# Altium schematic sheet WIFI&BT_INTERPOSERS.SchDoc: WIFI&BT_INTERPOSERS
size A3; Author: P.A.; CompanyName: STMicroelectronics; Organization: Microcontrollers Division; Address1: 12, Rue Jules HOROWITZ; Address2: 38019 Grenoble; Address3: FRANCE; DocumentNumber: 13; Revision: C; SheetNumber: 13; SheetTotal: 16; Project: STM32L4S5AII6_IOT_V2; PageSetup: Record=PageOptions¦CenterHorizontal=True¦CenterVertical=True¦PrintScale=1.00¦XCorrection=1.00¦YCorrection=1.00¦PrintKind=1¦BorderSize=5000000¦LeftOffset=0¦BottomOffset=0¦Orientation=2¦PaperLength=1000¦PaperWidth=1000¦Scale=100¦PaperSource=7¦PrintQuality=-3¦MediaType=1¦DitherType=10¦PrintScaleMode=1¦PaperKind=Letter¦PaperIndex=1
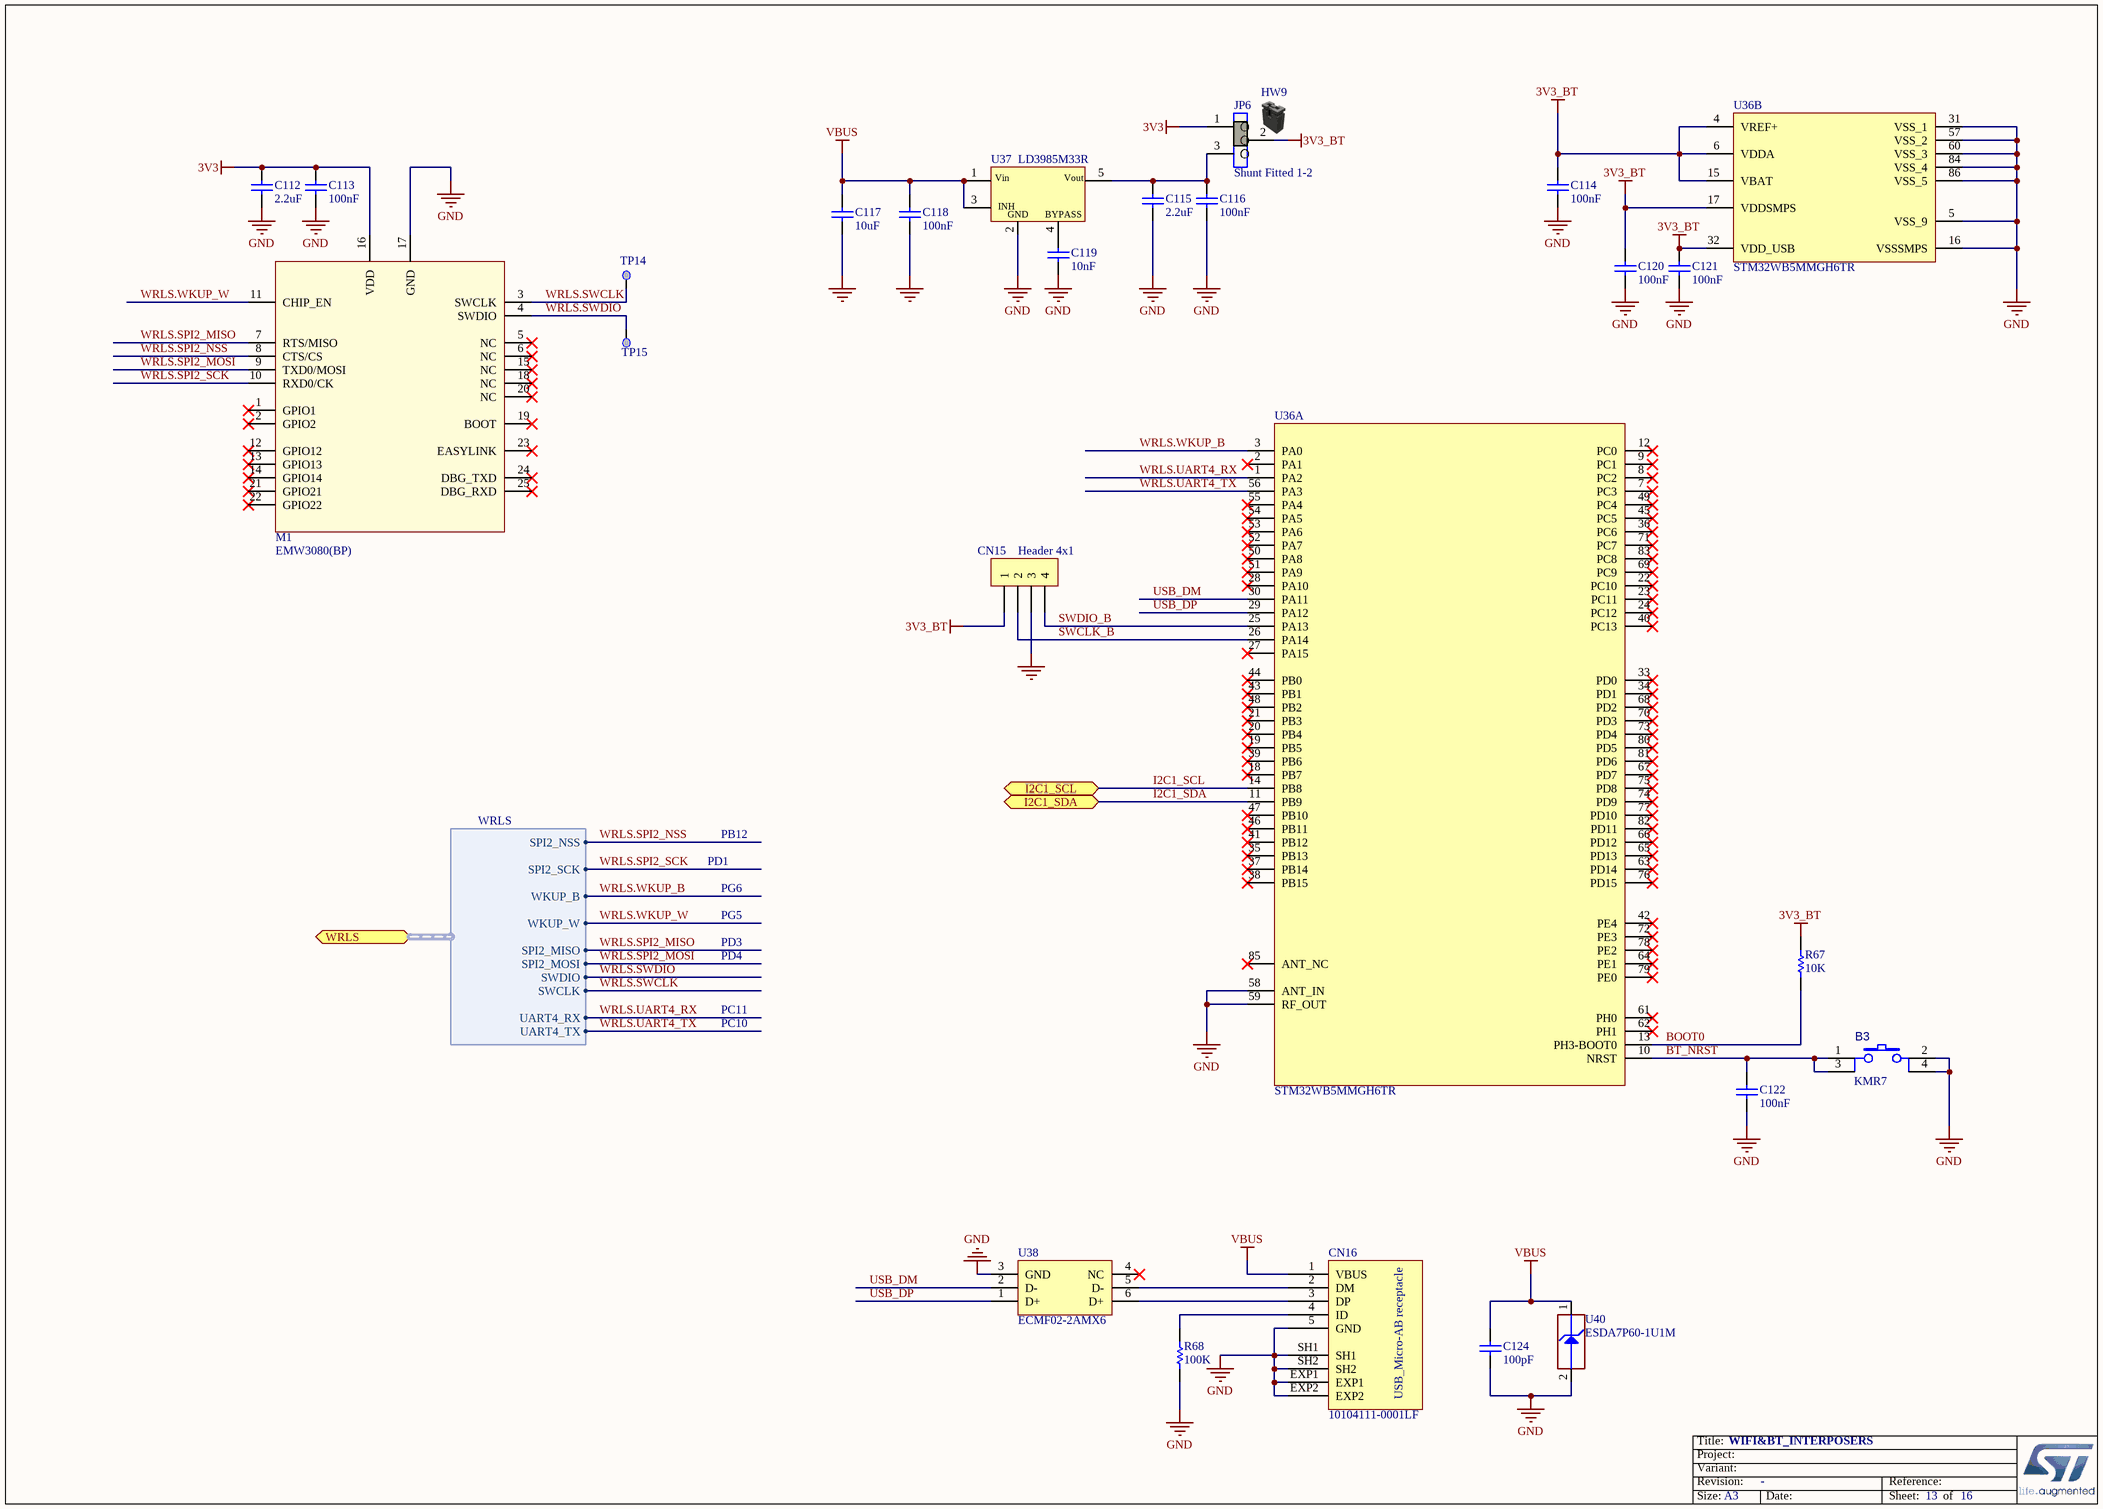
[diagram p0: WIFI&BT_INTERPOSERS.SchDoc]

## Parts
B3  value KMR7  [SWI_C&K_KMR721NG-LFS]  (hidden comment: SW-PUSH-CMS_KMR_NG)
C112  value 2.2uF  [C0603]  (hidden comment: Capacitor)
C113  value 100nF  [C0402]  (hidden comment: Capacitor)
C114  value 100nF  [C0402]
C115  value 2.2uF  [C0603]  (hidden comment: Capacitor)
C116  value 100nF  [C0402]  (hidden comment: Capacitor)
C117  value 10uF  [C0603]  (hidden comment: Capacitor)
C118  value 100nF  [C0402]  (hidden comment: Capacitor)
C119  value 10nF  [C0402]  (hidden comment: Capacitor)
C120  value 100nF  [C0402]
C121  value 100nF  [C0402]
C122  value 100nF  [C0402]
C124  value 100pF  [C0402]
CN15  Header 4x1  [CON_SAMTEC_TSW-104-07-G-S]
CN16  value 10104111-0001LF  [CON_USBMICROAB_FCI_10104111-0001LF]  (hidden comment: USB_uAB_10104111-0001LF)
HW9  Shunt Black 2.54mm  (value not drawn)  (mechanical)
JP6  Shunt Fitted 1-2  [CON_SAMTEC_TSW-103-07-F-S]
M1  EMW3080(BP)  [MOD_WIFI_MXCHIP_EMW3080-BP]
R67  value 10K  [R0402]
R68  value 100K  [R0402]  (hidden comment: Resistor)
TP14  Test Point  [TP_SMD_1MM]  (value not drawn)  (no BOM)
TP15  Test Point  [TP_SMD_1MM]  (value not drawn)  (no BOM)
U36  STM32WB5MMGH6TR  [MOD_DORY_STM_86P_7P3X11_H1P342]  (parts A,B of 2)
U37  LD3985M33R  [REG_SOT23-5L]
U38  ECMF02-2AMX6  [ESD_QFN-6L_1P7X1P5_P050]
U40  value ESDA7P60-1U1M  [ESD_QFN2_1P6X1_P125]  (hidden comment: ESD-TRANSIL)

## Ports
I2C1_SCL, I2C1_SDA, WRLS (harness WRLS)

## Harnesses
WRLS: WKUP_B, WKUP_W, SPI2_NSS, SPI2_SCK, SPI2_MISO, SPI2_MOSI, SWDIO, SWCLK, UART4_RX, UART4_TX

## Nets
3V3: C112.2 C113.2 JP6.1 M1.16(VDD)
3V3_BT: C114.2 C120.2 C121.2 CN15.1 JP6.2 R67.2 U36.4(VREF+) U36.6(VDDA) U36.15(VBAT) U36.17(VDDSMPS) U36.32(VDD_USB)
GND: B3.2 B3.4 C112.1 C113.1 C114.1 C115.1 C116.1 C117.1 C118.1 C119.2 C120.1 C121.1 C122.1 C124.1 CN15.3 CN16.5(GND) CN16.EXP1 CN16.EXP2 CN16.SH1 CN16.SH2 M1.17(GND) R68.1 U36.5(VSS_9) U36.16(VSSSMPS) U36.31(VSS_1) U36.57(VSS_2) U36.58(ANT_IN) U36.59(RF_OUT) U36.60(VSS_3) U36.84(VSS_4) U36.86(VSS_5) U37.2(GND) U38.3(GND) U40.2(GND)
VBUS: C117.2 C118.2 C124.2 CN16.1(VBUS) U37.1(Vin) U37.3(CE) U40.1(IO1)
BOOT0: R67.1 U36.13(PH3-BOOT0)
BT_NRST: B3.1 B3.3 C122.2 U36.10(NRST)
I2C1_SCL: U36.14(PB8) ; port I2C1_SCL
I2C1_SDA: U36.11(PB9) ; port I2C1_SDA
SWCLK_B: CN15.2 U36.26(PA14)
SWDIO_B: CN15.4 U36.25(PA13)
USB_DM: U36.30(PA11) U38.2(D-)
USB_DP: U36.29(PA12) U38.1(D+)
WRLS.SPI2_MISO: M1.7(RTS/MISO) ; port WRLS.SPI2_MISO
WRLS.SPI2_MOSI: M1.9(TXD0/MOSI) ; port WRLS.SPI2_MOSI
WRLS.SPI2_NSS: M1.8(CTS/CS) ; port WRLS.SPI2_NSS
WRLS.SPI2_SCK: M1.10(RXD0/CK) ; port WRLS.SPI2_SCK
WRLS.SWCLK: M1.3(SWCLK) TP14.1 ; port WRLS.SWCLK
WRLS.SWDIO: M1.4(SWDIO) TP15.1 ; port WRLS.SWDIO
WRLS.UART4_RX: U36.1(PA2) ; port WRLS.UART4_RX
WRLS.UART4_TX: U36.56(PA3) ; port WRLS.UART4_TX
WRLS.WKUP_B: U36.3(PA0) ; port WRLS.WKUP_B
WRLS.WKUP_W: M1.11(CHIP_EN) ; port WRLS.WKUP_W
NetC115_2: C115.2 C116.2 JP6.3 U37.5(Vout)
NetC119_1: C119.1 U37.4(BYPASS)
NetCN16_2: CN16.2(DM) U38.5(D-)
NetCN16_3: CN16.3(DP) U38.6(D+)
NetCN16_4: CN16.4(ID) R68.2

Not connected (* = marked no-connect by the designer): M1 1(GPIO1)* 2(GPIO2)* 5(NC)* 6(NC)* 12(GPIO12)* 13(GPIO13)* 14(GPIO14)* 15(NC)* 18(NC)* 19(BOOT)* 20(NC)* 21(GPIO21)* 22(GPIO22)* 23(EASYLINK)* 24(DBG_TXD)* 25(DBG_RXD)*; U36 2(PA1)* 7(PC3)* 8(PC2)* 9(PC1)* 12(PC0)* 18(PB7)* 19(PB5)* 20(PB4)* 21(PB3)* 22(PC10)* 23(PC11)* 24(PC12)* 27(PA15)* 28(PA10)* 33(PD0)* 34(PD1)* 35(PB13)* 36(PC6)* 37(PB14)* 38(PB15)* 39(PB6)* 40(PC13)* 41(PB12)* 42(PE4)* 43(PB1)* 44(PB0)* 45(PC5)* 46(PB11)* 47(PB10)* 48(PB2)* 49(PC4)* 50(PA8)* 51(PA9)* 52(PA7)* 53(PA6)* 54(PA5)* 55(PA4)* 61(PH0)* 62(PH1)* 63(PD14)* 64(PE1)* 65(PD13)* 66(PD12)* 67(PD7)* 68(PD2)* 69(PC9)* 70(PD3)* 71(PC7)* 72(PE3)* 73(PD4)* 74(PD9)* 75(PD8)* 76(PD15)* 77(PD10)* 78(PE2)* 79(PE0)* 80(PD5)* 81(PD6)* 82(PD11)* 83(PC8)* 85(ANT_NC)*; U38 4(NC)*

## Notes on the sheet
- PB12
- PD1
- PG5
- PG6
- PD4
- PD3
- PC10
- PC11

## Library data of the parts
B3 = MCD-01510: Microminiature SMT Top, 2N, N.O., IP67; Part_Type: Misc; Manufacturer_Part_Number: KMR721NG LFS; Manufacturer: C&K; Provided_By: SUBCO
C112 = MCD-00012: Capacitor, MLCC, 2.2uF, 10V, X5R, 10%, 0603, T=0,8mm; Manufacturer_Part_Number: CC0603KRX5R6BB225; Manufacturer: YAGEO; Alternate_Manufacturer_Part_Number: C0603C225K8PACTU; Alternate_Manufacturer: KEMET; Provided_By: SUBCO
C113 = MCD-00006: Capacitor, MLCC, 100nF, 16V, X7R, 10%, 0402, T=0.5mm; Manufacturer_Part_Number: CC0402KRX7R7BB104; Manufacturer: YAGEO; Alternate_Manufacturer_Part_Number: GCM155R71C104KA55D; Alternate_Manufacturer: MURATA; ECCN_US: EAR99; ECCN_EU: NEC; Provided_By: SUBCO
C114 C120-C122 = MCD-00006: Capacitor, MLCC, 100nF, 16V, X7R, 10%, 0402, T=0.5mm; Manufacturer_Part_Number: CC0402KRX7R7BB104; Manufacturer: YAGEO; Alternate_Manufacturer_Part_Number: GCM155R71C104KA55D; Alternate_Manufacturer: MURATA; Provided_By: SUBCO; ECCN_US: EAR99; ECCN_EU: NEC
C115 = MCD-00012: Capacitor,2.2uF,10V, X5R,10%,0603,YAGEO; Manufacturer_Part_Number: CC0603KRX5R6BB225; Alternate_Manufacturer_Part_Number: C0603C225K8PACTU; Alternate_Manufacturer: KEMET; Provided_By: Subcon
C116 C118 = MCD-00006: Capacitor,100nF,16V,X7R,10%,0402,YAGEO; Manufacturer_Part_Number: CC0402KRX7R7BB104; Provided_By: Subcon
C117 = MCD-00243: Capacitor,10uF,6V3,X5R,10%,0603,YAGEO; Manufacturer_Part_Number: CC0603KRX5R5BB106; Provided_By: Subcon
C119 = MCD-00011: Capacitor,10nF,16V,X7R,10%,0402,YAGEO; Manufacturer_Part_Number: CC0402KRX7R7BB103; Provided_By: Subcon
C124 = MCD-00205: Capacitor, MLCC, 100pF, 50V, NPO, 5%, 0402, T=0,5mm; Manufacturer_Part_Number: CC0402JRNPO9BN101; Manufacturer: YAGEO; Provided_By: Subcon; Initial_Board_Reference: MB1361
CN15 = MCD-00029: Header, 4x1, 2,54mm, VR, TH, Height 5.84mm/2.54mm; Manufacturer_Part_Number: TSW-104-07-x-S; Manufacturer: SAMTEC; Part_Type: Connector; Provided_By: Subcon; Initial_Board_Reference: MB1274
CN16 = MCD-01075: USB, micro AB receptacle,10104111-0001LF; Part_Type: Connector; Manufacturer: FCI; Provided_By: SUBCO
HW9 = MCD-00043: SHUNT 2.54mm BLACK; Part_Type: Mechanical; Manufacturer: SAMTEC; Value: SNT-100-BK-G; Provided_By: SUBCO; Initial_Board_Reference: MB1274; Item Type: Item; Path: ws/MCD_ApplicationBoards/Lists/MCDPARTSdatabase
JP6 = MCD-00684: Header, 3x1, 2,54mm, VR, TH, Height 5.84mm/2.54mm - Shunt Fitted 1-2 by default; Part_Type: Connector; Manufacturer_Part_Number: TSW-103-07-F-S; Manufacturer: SAMTEC; Provided_By: Subcon; Initial_Board_Reference: MB1331
M1 = MCD-01500: Wi-Fi module 33x18mm, UART-SPI interface; Part_Type: IC; Manufacturer: MXCHIP; Provided_By: SUBCO
R67 = MCD-00053: Resistor,10K,0402,1%,1/16W; Manufacturer_Part_Number: RC0402FR-0710KL; Manufacturer: YAGEO; Provided_By: subcon; Initial_Board_Reference: MB1274
R68 = MCD-00059: Resistor,100K,0402,1%,1/16W; Manufacturer_Part_Number: RC0402FR-07100KL; Manufacturer: YAGEO; Alternate_Manufacturer_Part_Number: RT0402FRE07100KL; ECCN_US: EAR99; ECCN_EU: NEC; Provided_By: SUBCO
TP14 TP15 = MCD-00074: Test Point 1mm; Part_Type: Mechanical
U36 = MCD-01965: STM32 module BLE oriented  based on DORY STM32WB55; Part_Type: Misc; Manufacturer: STMICROELECTRONICS
U37 = MCD-00086: Ultra low drop-low noise BiCMOS voltage, regulators low ESR capacitors compatible; Manufacturer: STM; ECCN_US: EAR99; ECCN_EU: NEC
U38 = MCD-00649: Common mode filter with ESD protection for USB 2.0 interface; Part_Type: Diode; Manufacturer: STMICROELECTRONICS; BMS_Part_Number: 9151138; ECCN_US: EAR99; ECCN_EU: NEC; Provided_By: SUBCO with ST control
U40 = MCD-00251: High power transient voltage suppressor, 7V breakdown; Part_Type: Diode; Manufacturer: STMICROELECTRONICS; BMS_Part_Number: 9179042; ECCN_US: EAR99; ECCN_EU: NEC; Provided_By: SUBCO with ST control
